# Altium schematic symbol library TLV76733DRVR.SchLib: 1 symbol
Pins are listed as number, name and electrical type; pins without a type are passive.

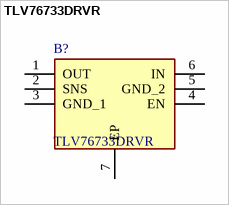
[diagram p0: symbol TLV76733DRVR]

## TLV76733DRVR
designator B?
Adjustable and fixed 1-A 16-V positive-voltage low-dropout (LDO) linear regulator; Manufacturer_Name: Texas Instruments; Geometry.Height: 0.8mm
footprint SON65P200X200X80-7N
pins: 1 OUT, 2 SNS, 3 GND_1, 4 EN, 5 GND_2, 6 IN, 7 EP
